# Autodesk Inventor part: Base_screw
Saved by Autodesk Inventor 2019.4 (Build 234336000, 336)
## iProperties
Created: 2019-10
Part Number: Base_screw
Material: Generic
Document SubType Name: Modeling
Designer: Administrator
Density: 1 g/cm^3
Appearance: Default
Title: Base_screw
Author: Administrator
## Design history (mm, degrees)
feature "Body1"
body "Solid1"
